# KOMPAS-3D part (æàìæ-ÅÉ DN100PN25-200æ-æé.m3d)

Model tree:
1. Объединить компоненты:1  (labels: СЕНС-ПР DN100PN25-200С)
2. Эскиз:1
3. Операция выдавливания:1
     Расстояние 1 = 14
4. Фаска:1
     Угол = 45; Длина 1 = 2; Длина 2 = 2

Referenced files in D:\Савин\!СЕНСОР\3D для заказчика\!Новый перечень\СЕНС-ПР\2. СЕНС-ПР-200С\DN100\: СЕНС-ПР DN100PN25-200С.a3d
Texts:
  СЕНС-ПР DN100PN25-200С-СВ
  ООО НПП Сенсор
  СЕНС-ПР DN100PN25-200С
